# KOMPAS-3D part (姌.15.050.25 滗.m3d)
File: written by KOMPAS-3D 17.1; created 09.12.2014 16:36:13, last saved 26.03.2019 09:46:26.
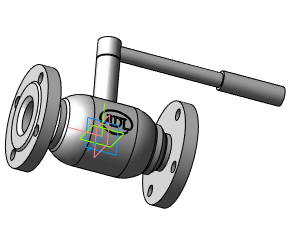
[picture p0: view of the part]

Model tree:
1. Операция без истории:4  (labels: Сталь 20  ГОСТ 1050-88)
